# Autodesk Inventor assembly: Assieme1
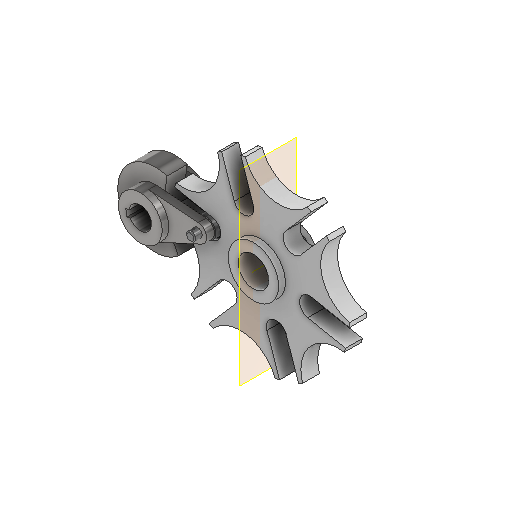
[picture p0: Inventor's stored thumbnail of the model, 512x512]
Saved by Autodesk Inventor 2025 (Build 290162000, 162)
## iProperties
Created: 2025-10
Part Number: Assieme1
Document SubType Name: Assembly
Designer: Ryzen5700u
Author: Ryzen5700u
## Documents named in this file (3)
- C:\Users\Ryzen5700u\Desktop\trasm. croce di malta\Assieme1.iam
- C:\Users\Ryzen5700u\Desktop\trasm. croce di malta\Assieme bielletta.iam
- C:\Users\Ryzen5700u\Desktop\trasm. croce di malta\croce di malta.ipt
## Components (2 placed, 2 different names)
1. Assieme bielletta:1 [sub-assembly] — Coincidente:1, Allineato:1, Coincidente:2
2. croce di malta:1 — Coincidente:2, Coincidente:3, Coincidente:4, Coincidente:5, Coincidente:6
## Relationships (7: Mate 6, Flush 1)
- Coincidente:1 [Mate]: Assieme bielletta:1
- Allineato:1 [Flush]: Assieme bielletta:1
- Coincidente:2 [Mate]: Assieme bielletta:1 ↔ croce di malta:1
- Coincidente:3 [Mate]: croce di malta:1
- Coincidente:4 [Mate]: croce di malta:1
- Coincidente:5 [Mate]: croce di malta:1
- Coincidente:6 [Mate]: croce di malta:1
